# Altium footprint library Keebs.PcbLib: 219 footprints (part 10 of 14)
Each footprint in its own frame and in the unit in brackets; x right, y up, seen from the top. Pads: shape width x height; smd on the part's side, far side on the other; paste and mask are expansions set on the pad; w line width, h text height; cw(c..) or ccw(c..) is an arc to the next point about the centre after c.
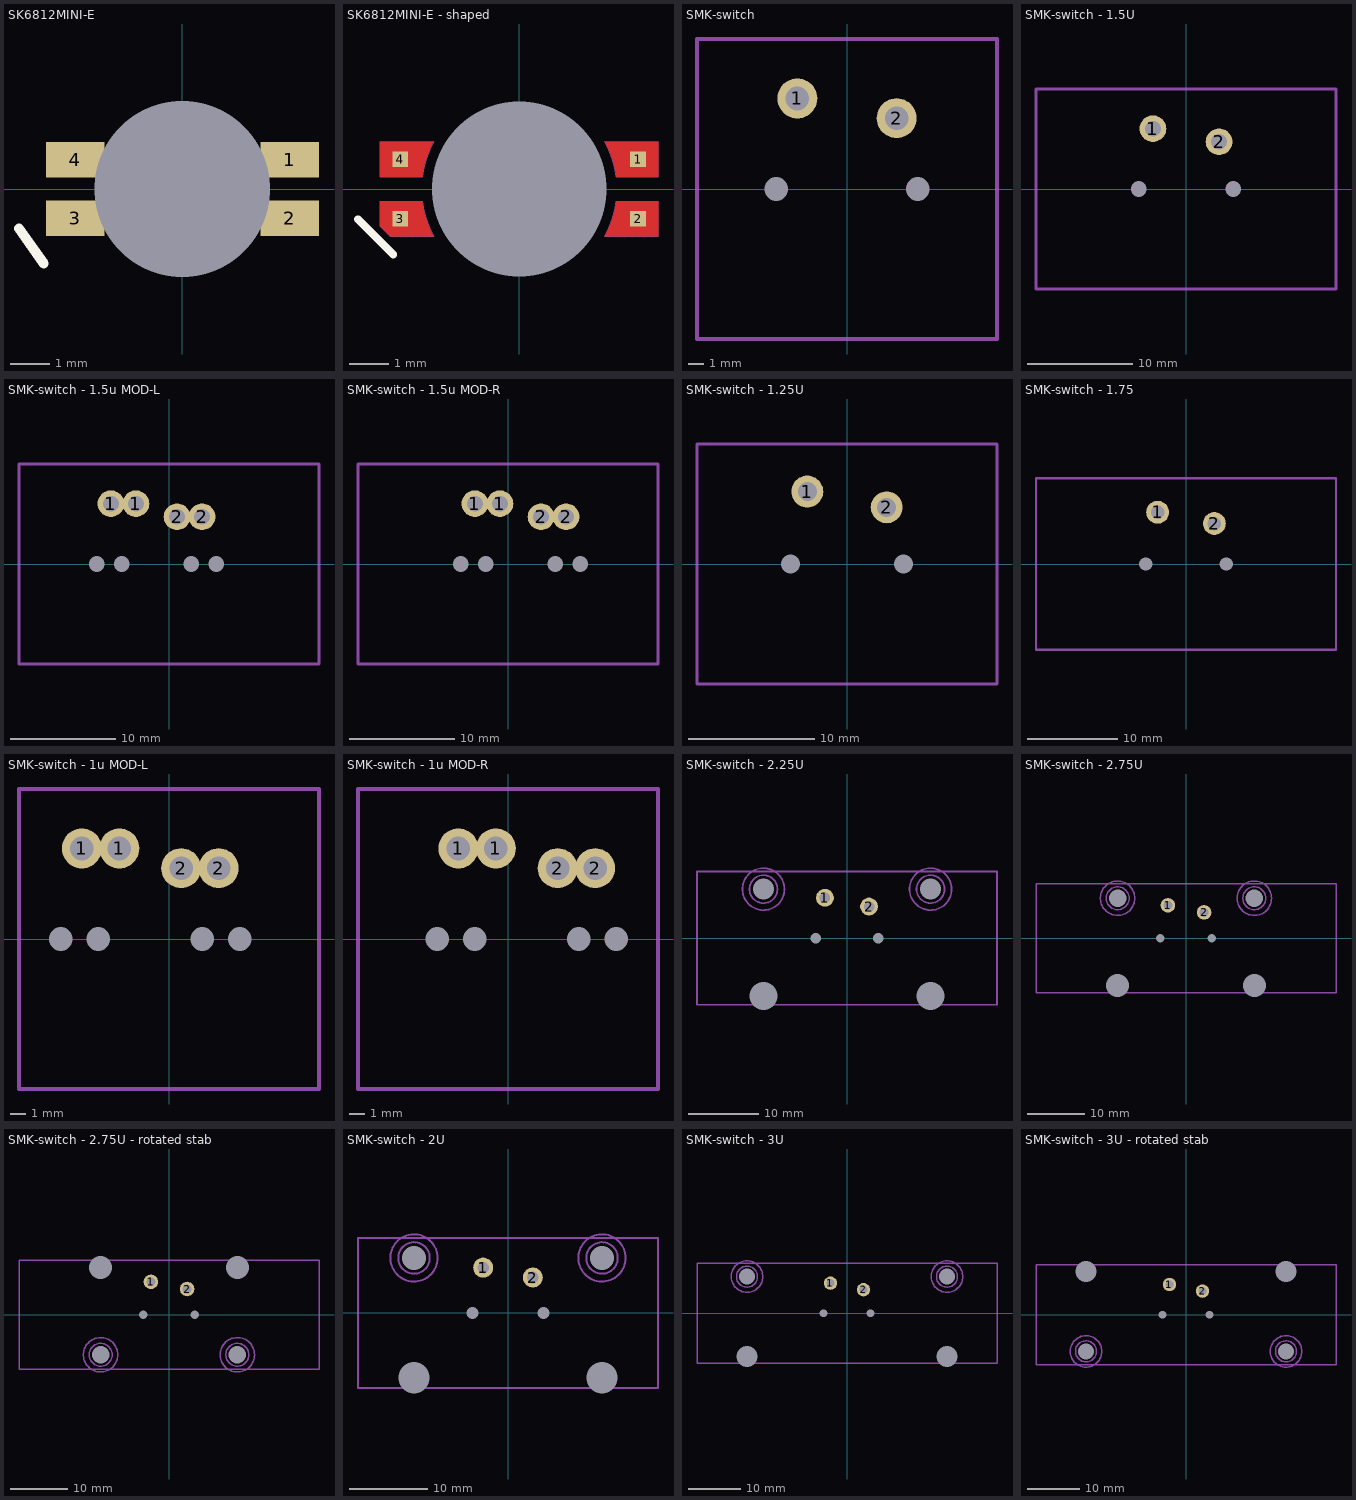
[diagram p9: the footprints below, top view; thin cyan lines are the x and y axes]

## SK6812MINI-E [mm]
pads (5):
  rect 1.5x0.9 smd: 1(2.75,0.75) 2(2.75,-0.75) 3(-2.75,-0.75) 4(-2.75,0.75)
  round 1 hole 4.5 unplated: ""(0,0)
Top Overlay:
  lines w0.254: -4.191,-1.016 -3.556,-1.905
Mechanical 13:
  lines w0.2: -1.6,-1.4 1.6,-1.4 1.6,1.4 -1.6,1.4 -1.6,-1.4
  text ".Designator" at -1.27,-0.127 h0.35
3D body "LED_SK6812MINI-E.step": height 0.94, standoff -0.84, extent -2.94,-1.403 2.94,1.397

## SK6812MINI-E - shaped [mm]
pads (5):
  rect 0.4x0.4 smd: 1(3,0.75) 2(3,-0.75) 3(-3,-0.75) 4(-3,0.75)
  round 1 hole 4.4 unplated: ""(0,0)
Top Layer:
  region: -3.5,0.304 -3.5,1.195 -2.157,1.195 -2.211,1.091 -2.305,0.875 -2.378,0.651 -2.43,0.421 -2.447,0.304 -2.449,0.304
  region: 2.447,0.304 2.43,0.421 2.378,0.651 2.305,0.875 2.211,1.091 2.157,1.195 3.5,1.195 3.5,0.304
  region: 2.157,-1.195 3.5,-1.195 3.5,-0.304 2.449,-0.304 2.447,-0.304 2.43,-0.421 2.378,-0.651 2.305,-0.875 2.211,-1.091
  region: -3.25,-1.195 -3.5,-0.945 -3.5,-0.304 -2.449,-0.304 -2.447,-0.304 -2.43,-0.421 -2.378,-0.651 -2.305,-0.875 -2.211,-1.091 -2.157,-1.195
Top Overlay:
  lines w0.2: -4.064,-0.762 -3.175,-1.651
Mechanical 7:
  lines w0.01: -2.449,-0.304 -3.455,-0.304 -3.5,-0.304 -3.5,-0.945 -3.25,-1.195 -2.211,-1.195 -2.157,-1.195 cw(c0,0) -2.447,-0.304 ; -2.449,0.304 -3.455,0.304 -3.5,0.304 -3.5,0.349 -3.5,1.154 -3.5,1.195 -3.476,1.195 -2.211,1.195 -2.157,1.195 ccw(c0,0) -2.447,0.304 ; 2.447,-0.304 cw(c0,0) 2.157,-1.195 2.211,-1.195 3.476,-1.195 3.5,-1.195 3.5,-1.154 3.5,-0.349 3.5,-0.304 3.455,-0.304 2.449,-0.304 ; 2.447,0.304 ccw(c0,0) 2.157,1.195 2.211,1.195 3.476,1.195 3.5,1.195 3.5,1.154 3.5,0.349 3.5,0.304 3.455,0.304 2.449,0.304
Mechanical 13:
  lines w0.1: -1.6,-1.4 -1.6,1.4 1.6,1.4 1.6,-1.4 -1.6,-1.4
  text ".Designator" at -1.27,-0.127 h0.35
3D body "LED_SK6812MINI-E.step": height 0.94, standoff -0.84, extent -2.94,-1.403 2.94,1.397

## SMK-switch [mm]
pads (5):
  round 2.54 hole 1.5 mask-0.5: 1(-3.15,5.75) 2(3.15,4.5)
  round 1 hole 1.5 unplated: ""(-4.5,0) ""(4.5,0)
  round 1 on Mech13: ""(0,0)
Mechanical 13:
  lines w0.254: -9.525,-9.525 -9.525,9.525 9.525,9.525 9.525,-9.525 -9.525,-9.525
  text ".Designator" at -3.575,-3.7 h0.7

## SMK-switch - 1.5U [mm]
pads (5):
  round 2.54 hole 1.5 mask-0.5: 1(-3.15,5.75) 2(3.15,4.5)
  round 1 hole 1.5 unplated: ""(-4.5,0) ""(4.5,0)
  round 1 on Mech13: ""(0,0)
Mechanical 13:
  lines w0.254: -14.287,-9.525 14.287,-9.525 14.287,9.525 -14.287,9.525 -14.287,-9.525
  text ".Designator" at -3.825,-3.375 h0.7

## SMK-switch - 1.5u MOD-L [mm]
pads (10):
  round 2.54 hole 1.5 mask-0.5: 1(-5.531,5.75) 1(-3.15,5.75) 2(0.769,4.5) 2(3.15,4.5)
  round 1 hole 1.5 unplated: ""(-6.881,0) ""(-4.5,0) ""(2.119,0) ""(4.5,0)
  round 1 on Mech13: ""(-2.381,0) ""(0,0)
Mechanical 13:
  lines w0.254: -14.287,-9.525 -14.287,9.525 14.287,9.525 14.287,-9.525 -14.287,-9.525
  text ".Designator" at 2.9,2.625 h0.7

## SMK-switch - 1.5u MOD-R [mm]
pads (10):
  round 2.54 hole 1.5 mask-0.5: 1(-3.15,5.75) 1(-0.769,5.75) 2(3.15,4.5) 2(5.531,4.5)
  round 1 hole 1.5 unplated: ""(-4.5,0) ""(-2.119,0) ""(4.5,0) ""(6.881,0)
  round 1 on Mech13: ""(0,0) ""(2.381,0)
Mechanical 13:
  lines w0.254: -14.287,-9.525 14.287,-9.525 14.287,9.525 -14.287,9.525 -14.287,-9.525
  text ".Designator" at -10.675,-5.325 h0.7

## SMK-switch - 1.25U [mm]
pads (5):
  round 2.54 hole 1.5 mask-0.5: 1(-3.15,5.75) 2(3.15,4.5)
  round 1 hole 1.5 unplated: ""(-4.5,0) ""(4.5,0)
  round 1 on Mech13: ""(0,0)
Mechanical 13:
  lines w0.254: -11.906,-9.525 -11.906,9.525 11.906,9.525 11.906,-9.525 -11.906,-9.525
  text ".Designator" at -3.425,-3.425 h0.7

## SMK-switch - 1.75 [mm]
pads (5):
  round 2.54 hole 1.5 mask-0.5: 1(-3.15,5.75) 2(3.15,4.5)
  round 1 hole 1.5 unplated: ""(-4.5,0) ""(4.5,0)
  round 1 on Mech13: ""(0,0)
Mechanical 13:
  lines w0.254: -16.669,-9.525 -16.669,9.525 16.669,9.525 16.669,-9.525 -16.669,-9.525
  text ".Designator" at -3.825,-3.375 h0.7

## SMK-switch - 1u MOD-L [mm]
pads (10):
  round 2.54 hole 1.5 mask-0.5: 1(-5.531,5.75) 1(-3.15,5.75) 2(0.769,4.5) 2(3.15,4.5)
  round 1 hole 1.5 unplated: ""(-6.881,0) ""(-4.5,0) ""(2.119,0) ""(4.5,0)
  round 1 on Mech13: ""(-2.381,0) ""(0,0)
Mechanical 13:
  lines w0.254: -9.525,-9.525 -9.525,9.525 9.525,9.525 9.525,-9.525 -9.525,-9.525
  text ".Designator" at -1.925,-7.85 h0.7

## SMK-switch - 1u MOD-R [mm]
pads (10):
  round 2.54 hole 1.5 mask-0.5: 1(-3.15,5.75) 1(-0.769,5.75) 2(3.15,4.5) 2(5.531,4.5)
  round 1 hole 1.5 unplated: ""(-4.5,0) ""(-2.119,0) ""(4.5,0) ""(6.881,0)
  round 1 on Mech13: ""(0,0) ""(2.381,0)
Mechanical 13:
  lines w0.254: -9.525,-9.525 9.525,-9.525 9.525,9.525 -9.525,9.525 -9.525,-9.525
  text ".Designator" at -4.225,-8.325 h0.7

## SMK-switch - 2.25U [mm]
pads (9):
  round 2.54 hole 1.5 mask-0.5: 1(-3.15,5.75) 2(3.15,4.5)
  round 1.524 hole 4 unplated: ""(-11.938,-8.255) ""(11.938,-8.255)
  round 1.524 hole 3 unplated: ""(-11.938,6.985) ""(11.938,6.985)
  round 1 hole 1.5 unplated: ""(-4.5,0) ""(4.5,0)
  round 1 on Mech13: ""(0,0)
Mechanical 13:
  lines w0.254: -21.431,-9.525 21.431,-9.525 21.431,9.525 -21.431,9.525 -21.431,-9.525
  text ".Designator" at -3.825,-3.375 h0.7
Mechanical 15:
  circle w0.254: c-11.938,6.985 r3
  circle w0.254: c-11.938,6.985 r2
  circle w0.254: c11.938,6.985 r3
  circle w0.254: c11.938,6.985 r2

## SMK-switch - 2.75U [mm]
pads (9):
  round 2.54 hole 1.5 mask-0.5: 1(-3.15,5.75) 2(3.15,4.5)
  round 1.524 hole 4 unplated: ""(-11.938,-8.255) ""(11.938,-8.255)
  round 1.524 hole 3.048 unplated: ""(-11.938,6.985) ""(11.938,6.985)
  round 1 hole 1.5 unplated: ""(-4.5,0) ""(4.5,0)
  round 1 on Mech13: ""(0,0)
Mechanical 13:
  lines w0.254: -26.194,-9.525 -26.194,9.525 26.194,9.525 26.194,-9.525 -26.194,-9.525
  text ".Designator" at -3.825,-3.375 h0.7
Mechanical 15:
  circle w0.254: c11.938,6.985 r2
  circle w0.254: c11.938,6.985 r3
  circle w0.254: c-11.938,6.985 r2
  circle w0.254: c-11.938,6.985 r3

## SMK-switch - 2.75U - rotated stab [mm]
pads (9):
  round 2.54 hole 1.5 mask-0.5: 1(-3.15,5.75) 2(3.15,4.5)
  round 1.524 hole 3.048 unplated: ""(-11.938,-6.985) ""(11.938,-6.985)
  round 1.524 hole 4 unplated: ""(-11.938,8.255) ""(11.938,8.255)
  round 1 hole 1.5 unplated: ""(-4.5,0) ""(4.5,0)
  round 1 on Mech13: ""(0,0)
Mechanical 13:
  lines w0.254: -26.194,-9.525 -26.194,9.525 26.194,9.525 26.194,-9.525 -26.194,-9.525
  text ".Designator" at -3.825,-3.375 h0.7
Mechanical 15:
  circle w0.254: c-11.938,-6.985 r2
  circle w0.254: c-11.938,-6.985 r3
  circle w0.254: c11.938,-6.985 r2
  circle w0.254: c11.938,-6.985 r3

## SMK-switch - 2U [mm]
pads (9):
  round 2.54 hole 1.5 mask-0.5: 1(-3.15,5.75) 2(3.15,4.5)
  round 1.524 hole 4 unplated: ""(-11.938,-8.255) ""(11.938,-8.255)
  round 1.524 hole 3.048 unplated: ""(-11.938,6.985) ""(11.938,6.985)
  round 1 hole 1.5 unplated: ""(-4.5,0) ""(4.5,0)
  round 1 on Mech13: ""(0,0)
Mechanical 13:
  lines w0.254: -19.05,-9.525 19.05,-9.525 19.05,9.525 -19.05,9.525 -19.05,-9.525
  text ".Designator" at -3.825,-3.375 h0.7
Mechanical 15:
  circle w0.254: c11.938,6.985 r2
  circle w0.254: c11.938,6.985 r3
  circle w0.254: c-11.938,6.985 r2
  circle w0.254: c-11.938,6.985 r3

## SMK-switch - 3U [mm]
pads (9):
  round 2.54 hole 1.5 mask-0.5: 1(-3.15,5.75) 2(3.15,4.5)
  round 1.524 hole 4 unplated: ""(-19.05,-8.255) ""(19.05,-8.255)
  round 1.524 hole 3.048 unplated: ""(-19.05,6.985) ""(19.05,6.985)
  round 1 hole 1.5 unplated: ""(-4.5,0) ""(4.5,0)
  round 1 on Mech13: ""(0,0)
Mechanical 13:
  lines w0.254: -28.575,-9.525 -28.575,9.525 28.575,9.525 28.575,-9.525 -28.575,-9.525
  text ".Designator" at -3.825,-3.375 h0.7
Mechanical 15:
  circle w0.254: c19.05,6.985 r2
  circle w0.254: c19.05,6.985 r3
  circle w0.254: c-19.05,6.985 r2
  circle w0.254: c-19.05,6.985 r3

## SMK-switch - 3U - rotated stab [mm]
pads (9):
  round 2.54 hole 1.5 mask-0.5: 1(-3.15,5.75) 2(3.15,4.5)
  round 1.524 hole 3.048 unplated: ""(-19.05,-6.985) ""(19.05,-6.985)
  round 1.524 hole 4 unplated: ""(-19.05,8.255) ""(19.05,8.255)
  round 1 hole 1.5 unplated: ""(-4.5,0) ""(4.5,0)
  round 1 on Mech13: ""(0,0)
Mechanical 13:
  lines w0.254: -28.575,-9.525 28.575,-9.525 28.575,9.525 -28.575,9.525 -28.575,-9.525
  text ".Designator" at -3.825,-3.375 h0.7
Mechanical 15:
  circle w0.254: c-19.05,-6.985 r3
  circle w0.254: c-19.05,-6.985 r2
  circle w0.254: c19.05,-6.985 r3
  circle w0.254: c19.05,-6.985 r2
